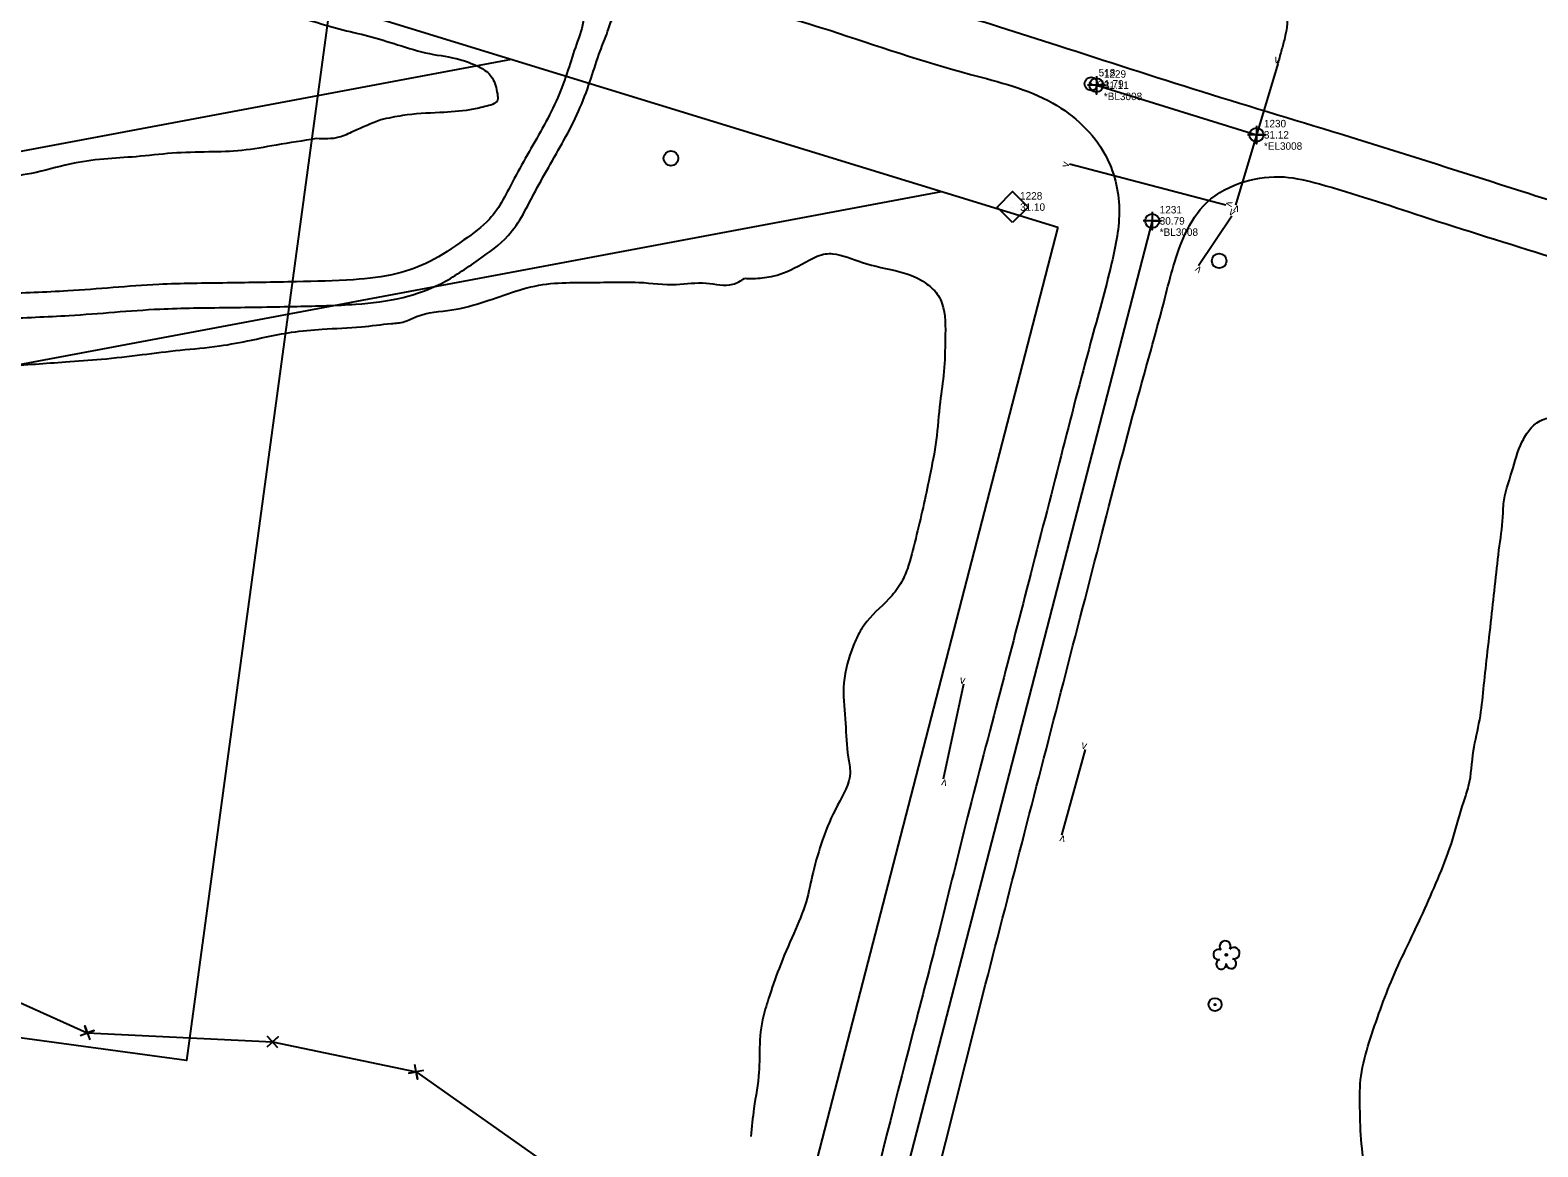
# Model space of a CAD drawing. Extents: x 2627243 to 2636458, y 566398 to 571062.
# Drawn here: x 2635397 to 2635901, y 568458 to 568831 of the extents above; entities that cross this region are included whole.
import ezdxf

# ---------------------------------------------------------------- set-up
doc = ezdxf.new("R2010")
doc.units = 0
for name, color, linetype in [('CTL Supplemental Horizontal CELL', 7, 'Continuous'), ('CTL Supplemental Horizontal Cogo Elevation', 7, 'Continuous'), ('CTL Supplemental Horizontal Cogo Number', 7, 'Continuous'), ('Default', 7, 'Continuous'), ('Exist DTM Crownline Cogo Point CELL', 7, 'Continuous'), ('Exist Hydro Stream or Body of Water', 7, 'Continuous'), ('Exist Other Culture Located Object CELL', 7, 'Continuous'), ('Exist Property Corner CELL', 7, 'Continuous'), ('Exist Property Iron Pin CELL', 7, 'Continuous'), ('Exist Property Iron Pin Cogo Elevation', 7, 'Continuous'), ('Exist Property Iron Pin Cogo Number', 7, 'Continuous'), ('Exist Property Line', 7, 'Continuous'), ('Exist Right of Way Easement Line', 7, 'Continuous'), ('Exist Right of Way Line', 7, 'Continuous'), ('Exist Roads EOP', 7, 'Continuous'), ('Exist Roads Soil', 7, 'Continuous'), ('Exist Structure Minor Culvert Topo', 7, 'Continuous'), ('Exist Utilities Other Pole CELL', 7, 'Continuous'), ('Exist Vegetation Tree CELL', 7, 'Continuous'), ('Exist Vegetation Woods Line', 7, 'Continuous'), ('Scratch_Level_2', 7, 'Continuous')]:
    doc.layers.add(name, color=color, linetype=linetype)

# ---------------------------------------------------------------- blocks, each defined once
blk = doc.blocks.new('EXIST PROPERTY IRON PIN')
at = {"layer": 'Exist Property Iron Pin CELL'}
for radius in [0.0441, 0.00141]:
    blk.add_circle((0, 0), radius, dxfattribs=at)
blk = doc.blocks.new('CTL SUPPLEMENTAL HORIZONTAL')
at = {"layer": 'CTL Supplemental Horizontal CELL'}
blk.add_line((0, 0), (0, 0), dxfattribs=at)
blk.add_lwpolyline([(0, -0.104), (-0.104, 0), (0, 0.104), (0.104, 0), (0, -0.104)], dxfattribs=at)
blk = doc.blocks.new('EXIST DTM CROWNLINE COGO POINT')
at = {"layer": 'Exist DTM Crownline Cogo Point CELL'}
blk.add_lwpolyline([(0, 0.06), (0, -0.06), (0, 0), (0.06, 0), (-0.06, 0)], dxfattribs=at)
blk.add_circle((0, 0), 0.0469, dxfattribs=at)
blk = doc.blocks.new('EXIST OTHER CULTURE LOCATED OBJECT')
at = {"layer": 'Exist Other Culture Located Object CELL'}
for radius in [0.0436, 0.0048]:
    blk.add_circle((0, 0), radius, dxfattribs=at)
blk = doc.blocks.new('EXIST VEGETATION TREE')
at = {"layer": 'Exist Vegetation Tree CELL'}
blk.add_line((0, 0), (0, 0), dxfattribs=at)
blk.add_circle((0, 0), 0.00652, dxfattribs=at)
for centre, radius, start, end in [((-0.052, 0.003), 0.0345, 62.6636, 279.3457), ((-0.008, 0.057), 0.0371, 330.1651, 219.7134), ((0.051, 0.012), 0.038, 257.1011, 134.1999), ((-0.034, -0.062), 0.0338, 111.5671, 6.231), ((0.033, -0.058), 0.034, 181.2822, 74.56)]:
    blk.add_arc(centre, radius, start, end, dxfattribs=at)
blk = doc.blocks.new('EXIST UTILITIES OTHER POLE')
at = {"layer": 'Exist Utilities Other Pole CELL'}
blk.add_circle((0, 0), 0.0493, dxfattribs=at)

msp = doc.modelspace()

# ---------------------------------------------------------------- linework, layer by layer
at = {"layer": 'Default'}
for p, q in [((2635753.56, 568813.08), (2635807.1, 568796.47)), ((2635772.25, 568767.67), (2635645.38, 568277.01))]:
    msp.add_line(p, q, dxfattribs=at)
at = {"layer": 'Exist Hydro Stream or Body of Water'}
msp.add_spline([(2635697.19, 569078.83), (2635701.61, 569078.77), (2635707.88, 569077.63), (2635713.52, 569074.1), (2635716.8, 569070.81), (2635721.69, 569060.72), (2635724.55, 569054.55), (2635732.07, 569045.55), (2635738.72, 569037.25), (2635746.04, 569028.86), (2635750.91, 569019.29), (2635757.89, 569010.47), (2635761.24, 569008.05), (2635764.77, 569002.94), (2635768.89, 568992.26), (2635771.66, 568984.14), (2635771.66, 568982.06), (2635774.23, 568971.52), (2635774.28, 568969.35), (2635769.98, 568958.63), (2635767.17, 568948.66), (2635766.15, 568944.45), (2635765.26, 568933.44), (2635765.14, 568931.38), (2635765.65, 568929.31), (2635768.06, 568925.44), (2635771.3, 568922.23), (2635780.91, 568915.95), (2635790.14, 568908.49), (2635798.83, 568899.94), (2635803.29, 568895.32), (2635806.99, 568892.51), (2635809.67, 568889.04), (2635810.76, 568884.94), (2635811.07, 568873.87), (2635812.69, 568863.03), (2635813.97, 568852.38), (2635816.22, 568841.21), (2635816.88, 568839.24), (2635816.46, 568828.32), (2635815.37, 568824.38), (2635814.27, 568820.23)], degree=3, dxfattribs=at)
at = {"layer": 'Exist Property Corner CELL'}
for p, q in [((2635416, 568496), (2635416, 568496)), ((2635478, 568493), (2635478, 568493)), ((2635526, 568483), (2635526, 568483))]:
    msp.add_line(p, q, dxfattribs=at)
for points in [[(2635413.66, 568495.12), (2635418.34, 568496.88), (2635416, 568496), (2635415.12, 568498.34), (2635416.88, 568493.66)], [(2635476.15, 568491.32), (2635479.85, 568494.68), (2635478, 568493), (2635476.32, 568494.85), (2635479.68, 568491.15)], [(2635528.46, 568483.43), (2635523.54, 568482.57), (2635526, 568483), (2635526.43, 568480.54), (2635525.57, 568485.46)]]:
    msp.add_lwpolyline(points, dxfattribs=at)
at = {"layer": 'Exist Property Line'}
for p, q in [((2635365, 568519), (2635416, 568496)), ((2635416, 568496), (2635478, 568493)), ((2635478, 568493), (2635526, 568483)), ((2635526, 568483), (2635570, 568452))]:
    msp.add_line(p, q, dxfattribs=at)
at = {"layer": 'Exist Right of Way Easement Line'}
for p, q in [((2635250.77, 568764.19), (2635557.9, 568821.77)), ((2634448.9, 568542.63), (2635701.81, 568777.53))]:
    msp.add_line(p, q, dxfattribs=at)
at = {"layer": 'Exist Right of Way Line'}
msp.add_line((2635074.38, 568970.41), (2635740.72, 568765.57), dxfattribs=at)
msp.add_lwpolyline([(2635740.72, 568765.57), (2635637.21, 568365.24)], dxfattribs=at)
at = {"layer": 'Exist Roads EOP'}
msp.add_line((2635671.04, 568332.55), (2635716.51, 568512.3), dxfattribs=at)
for points in [[(2635133.46, 568993.27), (2635198.85, 568973.26), (2635239.36, 568960.01), (2635248.88, 568959.46), (2635293.13, 568945.35), (2635367.48, 568922.3), (2635452.26, 568896.08), (2635526.55, 568873.61), (2635591.22, 568853.69), (2635664.39, 568831.49)], [(2636321.49, 568647.28), (2636274.56, 568660.4), (2636236.9, 568671.94), (2636206.38, 568681.32), (2636165.72, 568693.93), (2636122.46, 568707.35), (2636061.54, 568726.1), (2636006.66, 568743.24), (2635966.12, 568755.51), (2635895.9, 568777.5), (2635838.75, 568795.57), (2635788.98, 568810.81), (2635740.76, 568826.23), (2635701.63, 568838.58), (2635667.16, 568849.05)], [(2635664.39, 568831.49), (2635711.47, 568816.69), (2635739.03, 568807.05), (2635756.5, 568789.8), (2635761.19, 568771.66), (2635758.67, 568753.54), (2635751.63, 568726.94), (2635741.79, 568689.24), (2635730.96, 568647.13), (2635720.61, 568607.33), (2635709.81, 568565.65), (2635700.71, 568529.06), (2635692.3, 568496.56), (2635652.81, 568337.17)], [(2635716.51, 568512.3), (2635729.51, 568562.8), (2635742.53, 568613.11), (2635755.39, 568663.01), (2635768.17, 568711.29), (2635776.47, 568741.73), (2635783.32, 568763.3), (2635790.48, 568773.8), (2635803.24, 568780.83), (2635816.34, 568782.36), (2635828.18, 568780.03), (2635862.52, 568769.27), (2635905.74, 568755.61), (2635950.33, 568741.59), (2636006.37, 568724.26), (2636060.59, 568707.64), (2636105.4, 568693.76), (2636151.72, 568679.51), (2636219.19, 568658.55), (2636252.04, 568648.48), (2636282.52, 568639.48), (2636316.73, 568630.2)]]:
    msp.add_spline(points, degree=3, dxfattribs=at)
at = {"layer": 'Exist Roads Soil'}
for points in [[(2635571.91, 568859.64), (2635576.62, 568853.76), (2635578.9, 568849.62), (2635580.1, 568846.87), (2635581.4, 568842.64), (2635582.03, 568835.31), (2635579.67, 568826.8), (2635576.79, 568818.12), (2635573.37, 568808.95), (2635568.81, 568799.69), (2635558.82, 568781.82), (2635550.51, 568768.25), (2635542.01, 568761.32), (2635530.56, 568754.08), (2635519.64, 568750.07), (2635505.07, 568748.01), (2635485.97, 568747.3), (2635462.75, 568746.91), (2635439.88, 568746.4), (2635409.45, 568744.24), (2635387.04, 568743.22), (2635356.63, 568741.56), (2635334.95, 568740.38), (2635303.95, 568739.37), (2635279.14, 568738.01), (2635248.7, 568737.15), (2635241.06, 568737.16), (2635235.84, 568738.43), (2635231.69, 568740.79), (2635228.12, 568743.71), (2635225.91, 568747.07), (2635225.85, 568752.29), (2635227.78, 568760.6), (2635228.96, 568765.97)], [(2635224.2, 568709.54), (2635226.06, 568718.94), (2635227.3, 568724.04), (2635229.29, 568727.96), (2635230.99, 568728.71), (2635234.78, 568728.91), (2635238.09, 568728.71), (2635241.91, 568729.04), (2635250.47, 568729.02), (2635279.5, 568729.8), (2635304.31, 568731.16), (2635335.31, 568732.16), (2635357.08, 568733.35), (2635387.45, 568735.01), (2635409.93, 568736.03), (2635440.26, 568738.19), (2635462.91, 568738.69), (2635486.19, 568739.08), (2635505.8, 568739.82), (2635521.66, 568742.05), (2635534.22, 568746.67), (2635546.82, 568754.64), (2635556.79, 568762.76), (2635565.91, 568777.66), (2635576.09, 568795.87), (2635580.92, 568805.69), (2635584.54, 568815.38), (2635587.54, 568824.41), (2635590.04, 568830.98), (2635592.12, 568836.02), (2635594.53, 568838.76), (2635597.52, 568842.07), (2635602.81, 568846.3), (2635609.11, 568848.26)]]:
    msp.add_spline(points, degree=3, dxfattribs=at)
at = {"layer": 'Exist Structure Minor Culvert Topo'}
for points in [[(2635814.27, 568820.23), (2635800.12, 568772.94)], [(2635744.56, 568786.82), (2635796.85, 568773.01)], [(2635798.84, 568769.29), (2635787.73, 568752.68)], [(2635709.14, 568612.69), (2635702.26, 568580.88)], [(2635749.78, 568590.88), (2635741.92, 568562.18)]]:
    msp.add_lwpolyline(points, dxfattribs=at)
at = {"layer": 'Exist Vegetation Woods Line'}
for points in [[(2635492.54, 568795.19), (2635479.16, 568793.02), (2635467.7, 568791.24), (2635456.67, 568790.74), (2635444.39, 568790.29), (2635432.32, 568789.15), (2635421.48, 568788.36), (2635410.18, 568786.67), (2635397.28, 568783.56), (2635386.06, 568781.72), (2635376.17, 568780.08), (2635364.43, 568778.73), (2635354.05, 568777.2), (2635343.08, 568775.3), (2635331.15, 568771.98), (2635320.73, 568769.19), (2635311.09, 568766.47), (2635300.04, 568762.05), (2635289.92, 568757.8), (2635285.23, 568756.73), (2635277.84, 568756.03), (2635273.33, 568756.31), (2635268.92, 568758.09), (2635260.55, 568763.58), (2635257.74, 568766.77), (2635255.55, 568768.29), (2635251.24, 568769.93), (2635239.52, 568770.86), (2635235.08, 568771.38), (2635230.96, 568773.35), (2635219.39, 568777.05), (2635208.16, 568779.52), (2635196.47, 568781.08), (2635187.96, 568778.87), (2635186.7, 568780.55), (2635186.57, 568782.74), (2635188.8, 568787.42), (2635192.21, 568791.2), (2635196, 568797.68), (2635204.71, 568805.18), (2635209.91, 568815.01), (2635212.83, 568824.87), (2635214.04, 568829.53), (2635215.88, 568834.18), (2635222.09, 568844.04), (2635223.91, 568848.05), (2635225.59, 568858.58), (2635225.93, 568863.32), (2635228.75, 568866.72), (2635240.33, 568866.33), (2635249.72, 568867.45), (2635259.28, 568861.05), (2635261.39, 568860.31), (2635266.38, 568859.92), (2635272.62, 568861.13), (2635277.15, 568863.13), (2635280.65, 568866.76), (2635282.47, 568870.78), (2635283.53, 568875.35), (2635284.28, 568885.71), (2635286.48, 568895.73), (2635287.85, 568897.82), (2635292.22, 568898.08), (2635298.32, 568897.56), (2635308.38, 568894.97), (2635321.22, 568891.24), (2635332.17, 568885.92), (2635342.65, 568881.33), (2635352.8, 568878.6), (2635362.53, 568876.22), (2635372.41, 568873.94), (2635384.16, 568872.61), (2635393.86, 568869.6), (2635403.4, 568865.87), (2635414, 568861.77), (2635423.73, 568857.74), (2635435.77, 568853.3), (2635447.77, 568849.26), (2635457.61, 568845.71), (2635468.84, 568841.59), (2635480.23, 568838.19), (2635490.61, 568834.77), (2635500.22, 568831.91), (2635510.19, 568829.48), (2635519.8, 568826.62), (2635530.53, 568823.63), (2635540.61, 568821.68), (2635545.65, 568819.87), (2635548.04, 568818.69), (2635551.48, 568815.48), (2635553.17, 568810.14), (2635553.2, 568808.1), (2635549.01, 568805.9), (2635543.93, 568804.8), (2635533.96, 568803.93), (2635521.42, 568802.9), (2635514.24, 568801.52)], [(2635514.24, 568801.52), (2635504.96, 568797.58), (2635500.19, 568795.64), (2635492.54, 568795.19)], [(2635635.95, 568748.48), (2635638.09, 568748.41), (2635644.01, 568748.92), (2635647.62, 568749.8), (2635657.48, 568754.54), (2635662.99, 568756.66), (2635665.27, 568756.68), (2635675.29, 568753.8), (2635687.77, 568750.64), (2635690.87, 568749.73), (2635696.9, 568746.55), (2635700.74, 568742.58), (2635701.87, 568740.19), (2635703, 568728.18), (2635702.58, 568717.26), (2635701.29, 568707.04), (2635699.98, 568694.28), (2635697.74, 568681.98), (2635695.59, 568671.81), (2635693.13, 568661.45), (2635690.34, 568651.29), (2635688, 568646.22), (2635684.16, 568641.21), (2635675.85, 568632.47), (2635673.67, 568628.76), (2635671.62, 568623.88), (2635669, 568611.53), (2635669.64, 568599.63), (2635670.53, 568588.31), (2635671.19, 568583.11), (2635666.99, 568572.24), (2635662, 568560.64), (2635658.81, 568549.81), (2635656.46, 568539.93), (2635652.31, 568529.3), (2635647.41, 568517.56), (2635643.9, 568507.55), (2635641.87, 568500.39), (2635640.87, 568489.72), (2635640.69, 568482.93), (2635639, 568470.76), (2635638.01, 568461.36)], [(2634979.32, 568641.8), (2634980.63, 568646.32), (2634981.55, 568648.14), (2634985.24, 568651.47), (2634994.9, 568656.46), (2635004.37, 568658.46), (2635011.34, 568659.51), (2635016.11, 568659.8), (2635020.92, 568660.33), (2635025.28, 568659.96), (2635030.41, 568659.66), (2635033.28, 568660.01), (2635038.49, 568660.58), (2635043.87, 568661.87), (2635055.05, 568665.76), (2635066.46, 568669.58), (2635077.86, 568672.78), (2635090.08, 568675.66), (2635100.66, 568677.52), (2635111.86, 568680.39), (2635116.36, 568681.75), (2635121.09, 568682.44), (2635131.69, 568683.28), (2635142.99, 568683.33), (2635155.2, 568682.91), (2635166.08, 568683.31), (2635177.63, 568684.95), (2635188.53, 568687.63), (2635198.7, 568690.47), (2635209.66, 568693.39), (2635220.72, 568696.79), (2635226.08, 568697.46), (2635231.16, 568696.92), (2635233.27, 568696.17), (2635236.73, 568693.59), (2635240.99, 568688.42), (2635244.97, 568685.34), (2635251.79, 568684.65), (2635254.15, 568685.5), (2635260.06, 568690.22), (2635261.58, 568692.41), (2635266.5, 568702.69), (2635272.07, 568706.98), (2635276.68, 568708.83), (2635282.69, 568710.1), (2635294.34, 568710.58), (2635305.37, 568709.42), (2635316.43, 568707.87), (2635318.65, 568707.61), (2635329.83, 568709.85), (2635341.47, 568712.99), (2635353.33, 568715.44), (2635365.51, 568717.06), (2635376.11, 568717.91), (2635388.32, 568719.14), (2635398.63, 568719.8), (2635408.69, 568720.51), (2635420.7, 568721.41), (2635434.38, 568722.94), (2635447.04, 568724.45), (2635460.18, 568725.85), (2635470.91, 568727.8), (2635484.33, 568730.41), (2635494.59, 568731.45), (2635507.71, 568732.22), (2635517.74, 568733.33), (2635522.08, 568733.97), (2635526.16, 568735.69), (2635537.96, 568737.91), (2635549.01, 568740.68), (2635559.21, 568744.15), (2635569.66, 568746.55), (2635580.06, 568747.06), (2635590.1, 568747.15), (2635600.63, 568747.12), (2635613.02, 568746.41), (2635623.03, 568746.88), (2635631.94, 568746.47), (2635635.95, 568748.48)], [(2635827.64, 568399.87), (2635831.03, 568403.32), (2635837.07, 568413.3), (2635838.51, 568415.91), (2635841.58, 568425.63), (2635843.17, 568436.68), (2635843.49, 568447.11), (2635842.31, 568458.87), (2635841.73, 568471.02), (2635842.1, 568481.69), (2635844.85, 568492.88), (2635848.57, 568503.85), (2635852.72, 568514.48), (2635857.66, 568525.2), (2635863.43, 568537.52), (2635868.37, 568548.87), (2635872.83, 568560.95), (2635876.47, 568573.34), (2635878.09, 568578.56), (2635879.73, 568590.48), (2635881.8, 568600.8), (2635883.08, 568611.03), (2635884.28, 568622.03), (2635885.74, 568634.88), (2635887.05, 568647), (2635888.45, 568658.98), (2635889.65, 568669.98), (2635889.78, 568672.99), (2635892.58, 568683.78), (2635895.95, 568693.7), (2635898.62, 568697.94), (2635900.39, 568699.71), (2635905.27, 568701.84), (2635908.72, 568701.99), (2635914.77, 568700.71), (2635927.09, 568696.2), (2635937.73, 568692.04), (2635947.04, 568687.66), (2635956.85, 568683.18), (2635966.6, 568679.08), (2635977.29, 568675.17), (2635988.26, 568671.45), (2635999.44, 568668.07), (2636011.09, 568663.95), (2636023.71, 568660.26), (2636034.71, 568657.8), (2636045.95, 568655.93), (2636055.62, 568653.24), (2636067.49, 568650.72), (2636079.89, 568648.34), (2636091.95, 568646.17), (2636102.17, 568644.25), (2636114.23, 568642.07), (2636124.54, 568639.38), (2636134.28, 568637.56), (2636145.9, 568639.27), (2636153, 568640.55), (2636162.48, 568645.24), (2636164.92, 568646.62), (2636169.74, 568647.88), (2636180.16, 568646.3), (2636190.08, 568643.56), (2636201.64, 568640.22), (2636212.33, 568636.94), (2636222.1, 568633.48), (2636232.68, 568629.72), (2636243.1, 568627.51), (2636253.71, 568625.64), (2636266.68, 568622.38), (2636276.41, 568619.93), (2636288.99, 568616.63), (2636300.79, 568613.24), (2636310.51, 568609.54), (2636321.49, 568606.45), (2636323.19, 568606.09)]]:
    msp.add_spline(points, degree=3, dxfattribs=at)
at = {"layer": 'Scratch_Level_2'}
msp.add_lwpolyline([(2633945.71, 569750.8), (2635590.54, 569527.29), (2635449.16, 568486.85), (2633804.33, 568710.36)], close=True, dxfattribs=at)

# ---------------------------------------------------------------- block references
at = {"layer": 'CTL Supplemental Horizontal CELL', "xscale": 50, "yscale": 50}
msp.add_blockref('CTL SUPPLEMENTAL HORIZONTAL', (2635725.54, 568772.3), dxfattribs=at)
at = {"layer": 'Default', "xscale": 50, "yscale": 50}
for p in [(2635753.56, 568813.08), (2635807.1, 568796.47), (2635772.25, 568767.67)]:
    msp.add_blockref('EXIST DTM CROWNLINE COGO POINT', p, dxfattribs=at)
at = {"layer": 'Exist Other Culture Located Object CELL', "xscale": 50, "yscale": 50}
msp.add_blockref('EXIST OTHER CULTURE LOCATED OBJECT', (2635793.28, 568505.51), dxfattribs=at)
at = {"layer": 'Exist Property Iron Pin CELL', "xscale": 50, "yscale": 50}
msp.add_blockref('EXIST PROPERTY IRON PIN', (2635751.82, 568813.52), dxfattribs=at)
at = {"layer": 'Exist Utilities Other Pole CELL', "xscale": 50, "yscale": 50}
for p in [(2635611.24, 568788.61), (2635794.64, 568754.3)]:
    msp.add_blockref('EXIST UTILITIES OTHER POLE', p, dxfattribs=at)
at = {"layer": 'Exist Vegetation Tree CELL', "xscale": 50, "yscale": 50}
msp.add_blockref('EXIST VEGETATION TREE', (2635797.04, 568522.12), dxfattribs=at)

# ---------------------------------------------------------------- texts
at = {"layer": 'CTL Supplemental Horizontal Cogo Elevation'}
msp.add_text('31.10', height=2.5, dxfattribs=at).set_placement((2635728.04, 568771.05))
at = {"layer": 'CTL Supplemental Horizontal Cogo Number'}
msp.add_text('1228', height=2.5, dxfattribs=at).set_placement((2635728.04, 568774.8))
at = {"layer": 'Default'}
for s, p in [('1229', (2635756.06, 568815.58)), ('31.11', (2635756.06, 568811.83)), ('*BL3008', (2635756.06, 568808.08)), ('31.12', (2635809.6, 568795.22)), ('1230', (2635809.6, 568798.97)), ('*EL3008', (2635809.6, 568791.47)), ('1231', (2635774.75, 568770.17)), ('30.79', (2635774.75, 568766.42)), ('*BL3008', (2635774.75, 568762.67))]:
    msp.add_text(s, height=2.5, dxfattribs=at).set_placement(p)
at = {"layer": 'Exist Property Iron Pin Cogo Elevation'}
msp.add_text('31.79', height=2.5, dxfattribs=at).set_placement((2635754.32, 568812.27))
at = {"layer": 'Exist Property Iron Pin Cogo Number'}
msp.add_text('518', height=2.5, dxfattribs=at).set_placement((2635754.32, 568816.02))
at = {"layer": 'Exist Structure Minor Culvert Topo'}
for rotation, p in [(343.1023, (2635812.84, 568820.67)), (74.9606, (2635744.17, 568785.37)), (255.4423, (2635797.23, 568774.46)), (325.9762, (2635797.6, 568770.14)), (163.584, (2635801.57, 568772.52)), (146.4579, (2635788.98, 568751.85)), (347.5584, (2635707.67, 568613.02)), (344.438, (2635748.33, 568591.28)), (168.0401, (2635703.73, 568580.57)), (164.9197, (2635743.37, 568561.79))]:
    msp.add_text('v', height=2.65, rotation=rotation, dxfattribs=at).set_placement(p)

doc.saveas('drawing.dxf')
